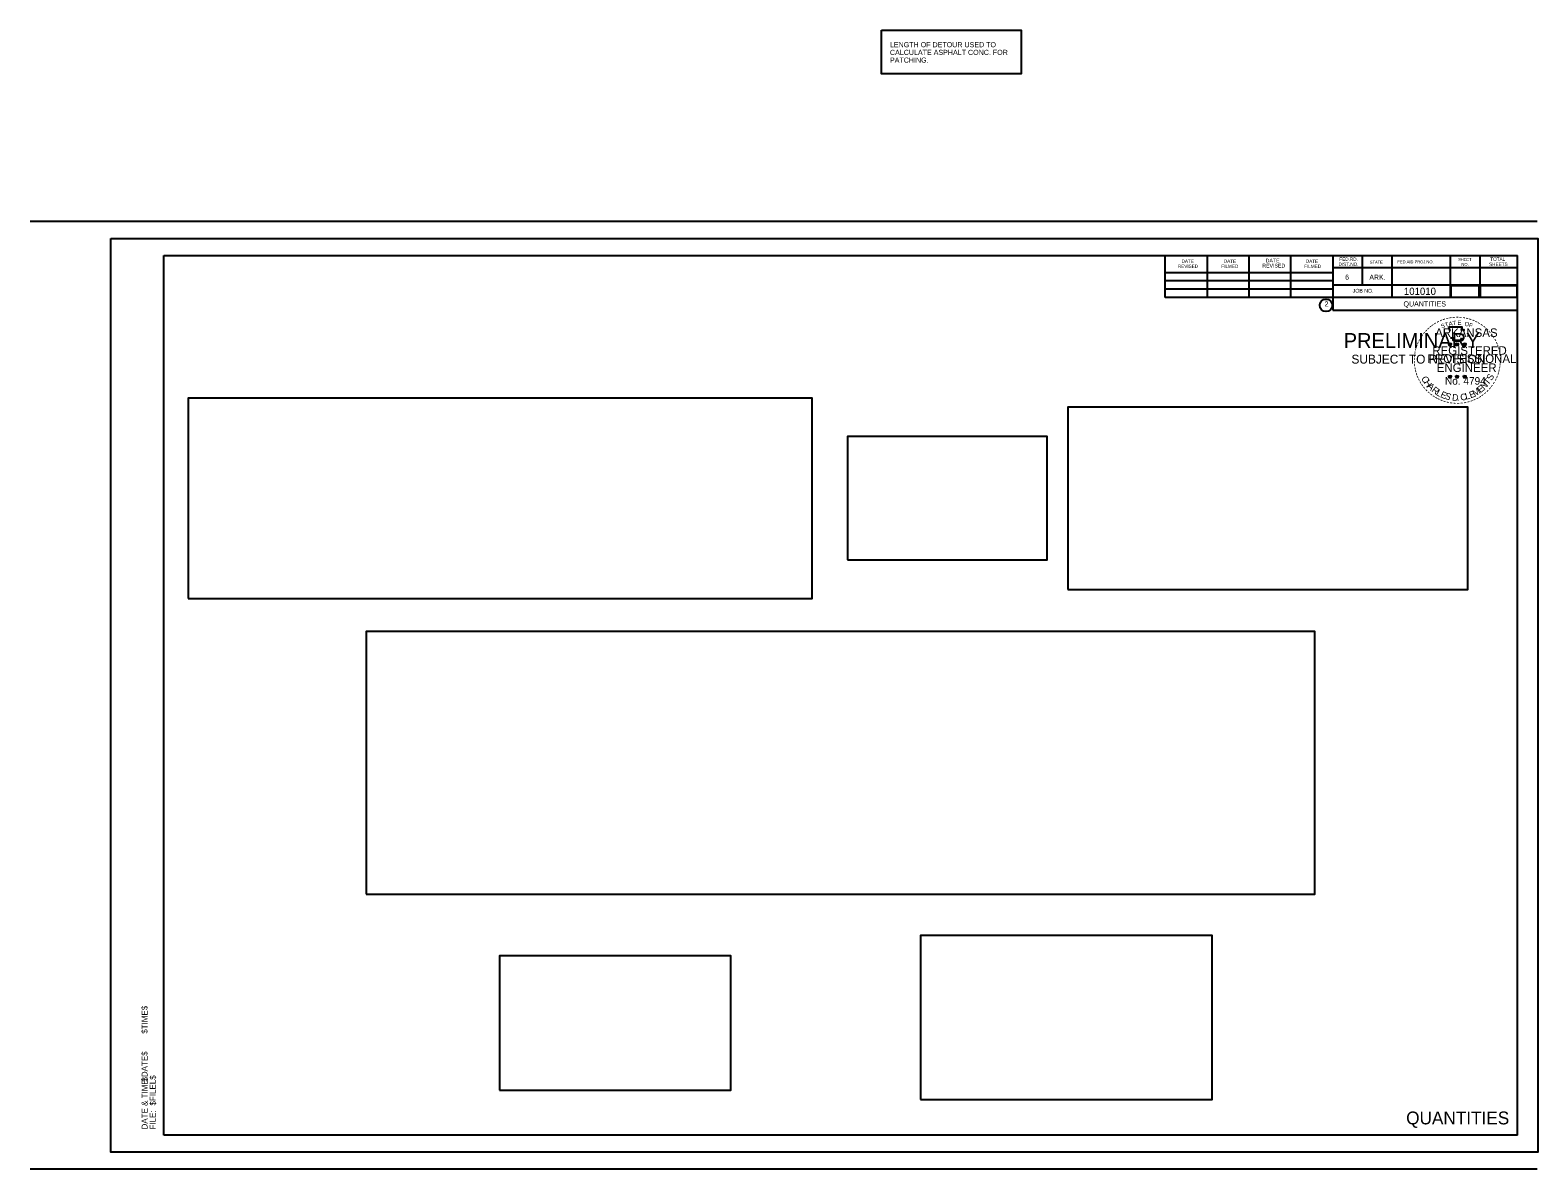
# Model space of a CAD drawing. Extents: x 9844 to 18514, y 8651 to 12569.
# Drawn here: x 13382 to 15142, y 9961 to 11290 of the extents above; entities that cross this region are included whole.
import ezdxf

# ---------------------------------------------------------------- set-up
doc = ezdxf.new("R2010")
doc.units = 0
for name, color, linetype in [('90% COMMENT', 7, 'Continuous'), ('Default', 7, 'Continuous'), ('Quantities', 7, 'Continuous'), ('R_Border Notes', 7, 'Continuous'), ('R_No Plot', 7, 'Continuous'), ('STAMP_PE_CRAFTON-SIGNATURE', 7, 'Continuous'), ('STAMP_PE_SEAL-INFO', 7, 'Continuous'), ('STAMP_PE_TXT', 7, 'Continuous'), ('STAMP_PRELIMINARY', 7, 'Continuous'), ('Total_Pages', 7, 'Continuous')]:
    doc.layers.add(name, color=color, linetype=linetype)

msp = doc.modelspace()

# ---------------------------------------------------------------- linework, layer by layer
at = {"layer": '90% COMMENT'}
msp.add_lwpolyline([(14375.9, 11290.3), (14539, 11290.3), (14539, 11239.1), (14375.9, 11239.1)], close=True, dxfattribs=at)
at = {"layer": 'Quantities'}
for points in [[(13566.2, 10626.8), (14294.8, 10626.8), (14294.8, 10860.6), (13566.2, 10860.6)], [(14593.6, 10637.2), (15060.8, 10637.2), (15060.8, 10850.2), (14593.6, 10850.2)], [(14336.3, 10671.6), (14569.6, 10671.6), (14569.6, 10815.8), (14336.3, 10815.8)], [(13774.3, 10281.4), (14882.1, 10281.4), (14882.1, 10588.1), (13774.3, 10588.1)], [(14421.4, 10041.5), (14762, 10041.5), (14762, 10233.2), (14421.4, 10233.2)], [(13929.7, 10052.3), (14199.9, 10052.3), (14199.9, 10209.4), (13929.7, 10209.4)]]:
    msp.add_lwpolyline(points, close=True, dxfattribs=at)
at = {"layer": 'R_No Plot'}
msp.add_lwpolyline([(15040.7, 10978.6), (15074, 10978.6), (15074, 10991.9), (15040.7, 10991.9)], close=True, dxfattribs=at)
at = {"layer": 'STAMP_PE_SEAL-INFO'}
msp.add_lwpolyline([(13475.8, 11046.8), (15142.5, 11046.8), (15142.5, 9980.1), (13475.8, 9980.1)], close=True, dxfattribs=at)
at = {"layer": 'STAMP_PE_TXT'}
for p, q in [((15038.1, 10924), (15039.8, 10923.5)), ((15038.1, 10924), (15039.4, 10923.8)), ((15038.1, 10924), (15039.3, 10923.4)), ((15038.8, 10922), (15039.8, 10923.5)), ((15038.8, 10922), (15039.4, 10923.2)), ((15038.8, 10922), (15039.8, 10923.1)), ((15039.8, 10925.3), (15039.6, 10924.1)), ((15039.8, 10923.5), (15039.8, 10925.3)), ((15039.8, 10925.3), (15040.1, 10924.1)), ((15041.6, 10924), (15039.8, 10923.5)), ((15040.9, 10922), (15039.8, 10923.5)), ((15040.9, 10922), (15039.8, 10923.1)), ((15041.6, 10924), (15040.2, 10923.8)), ((15040.9, 10922), (15040.2, 10923.5)), ((15041.6, 10924), (15040.6, 10923.5)), ((15046.5, 10924), (15048.2, 10923.5)), ((15046.5, 10924), (15047.7, 10923.8)), ((15046.5, 10924), (15047.6, 10923.4)), ((15047.1, 10922), (15048.2, 10923.5)), ((15047.1, 10922), (15047.7, 10923.2)), ((15047.1, 10922), (15048.2, 10923.1)), ((15048.2, 10925.3), (15048, 10924.1)), ((15048.2, 10923.5), (15048.2, 10925.3)), ((15048.2, 10925.3), (15048.4, 10924.1)), ((15049.9, 10924), (15048.2, 10923.5)), ((15049.3, 10922), (15048.2, 10923.5)), ((15049.3, 10922), (15048.2, 10923.1)), ((15049.9, 10924), (15048.5, 10923.8)), ((15049.3, 10922), (15048.6, 10923.5)), ((15049.9, 10924), (15048.9, 10923.5)), ((15055.3, 10924), (15057, 10923.4)), ((15055.3, 10924), (15056.5, 10923.8)), ((15055.3, 10924), (15056.5, 10923.4)), ((15055.9, 10921.9), (15057, 10923.4)), ((15055.9, 10921.9), (15056.6, 10923.2)), ((15055.9, 10921.9), (15057, 10923)), ((15057, 10925.3), (15056.8, 10924)), ((15057, 10923.4), (15057, 10925.3)), ((15057, 10925.3), (15057.3, 10924)), ((15058.8, 10924), (15057, 10923.4)), ((15058.1, 10921.9), (15057, 10923.4)), ((15058.1, 10921.9), (15057, 10923)), ((15058.8, 10924), (15057.3, 10923.7)), ((15058.1, 10921.9), (15057.4, 10923.4)), ((15058.8, 10924), (15057.7, 10923.5)), ((15038.1, 10886.2), (15039.8, 10885.6)), ((15038.1, 10886.2), (15039.3, 10886)), ((15038.1, 10886.2), (15039.3, 10885.6)), ((15038.7, 10884.1), (15039.8, 10885.6)), ((15038.7, 10884.1), (15039.4, 10885.4)), ((15038.7, 10884.1), (15039.8, 10885.2)), ((15039.8, 10887.4), (15039.6, 10886.2)), ((15039.8, 10885.6), (15039.8, 10887.4)), ((15039.8, 10887.4), (15040.1, 10886.2)), ((15041.6, 10886.2), (15039.8, 10885.6)), ((15040.9, 10884.1), (15039.8, 10885.6)), ((15040.9, 10884.1), (15039.8, 10885.2)), ((15041.6, 10886.2), (15040.1, 10885.9)), ((15040.9, 10884.1), (15040.2, 10885.6)), ((15041.6, 10886.2), (15040.5, 10885.7)), ((15046.4, 10886.2), (15048.2, 10885.6)), ((15046.4, 10886.2), (15047.7, 10886)), ((15046.4, 10886.2), (15047.6, 10885.6)), ((15047.1, 10884.1), (15048.2, 10885.6)), ((15047.1, 10884.1), (15047.7, 10885.4)), ((15047.1, 10884.1), (15048.2, 10885.2)), ((15048.2, 10887.4), (15048, 10886.2)), ((15048.2, 10885.6), (15048.2, 10887.4)), ((15048.2, 10887.4), (15048.4, 10886.2)), ((15049.9, 10886.2), (15048.2, 10885.6)), ((15049.2, 10884.1), (15048.2, 10885.6)), ((15049.2, 10884.1), (15048.2, 10885.2)), ((15049.9, 10886.2), (15048.5, 10885.9)), ((15049.2, 10884.1), (15048.6, 10885.6)), ((15049.9, 10886.2), (15048.9, 10885.7)), ((15055.3, 10886.1), (15057, 10885.6)), ((15055.3, 10886.1), (15056.5, 10885.9)), ((15055.3, 10886.1), (15056.4, 10885.5)), ((15055.9, 10884.1), (15057, 10885.6)), ((15055.9, 10884.1), (15056.6, 10885.3)), ((15055.9, 10884.1), (15057, 10885.2)), ((15057, 10887.4), (15056.8, 10886.1)), ((15057, 10885.6), (15057, 10887.4)), ((15057, 10887.4), (15057.3, 10886.1)), ((15058.7, 10886.1), (15057, 10885.6)), ((15058.1, 10884.1), (15057, 10885.6)), ((15058.1, 10884.1), (15057, 10885.2)), ((15058.7, 10886.1), (15057.3, 10885.9)), ((15058.1, 10884.1), (15057.4, 10885.5)), ((15058.7, 10886.1), (15057.7, 10885.6))]:
    msp.add_line(p, q, dxfattribs=at)
for points in [[(15038.3, 10943.4), (15039.7, 10939.3)], [(15055.9, 10938.8), (15056.6, 10940.2), (15053.1, 10940.1), (15053.9, 10943.4), (15038.3, 10943.4)], [(15039.8, 10925.3), (15040.9, 10922), (15038.1, 10924), (15041.6, 10924), (15038.8, 10922), (15039.8, 10925.3)], [(15040.8, 10931.3), (15040.8, 10930.9), (15043.6, 10930.8), (15043.3, 10928.4), (15052.7, 10928.4), (15053.7, 10931.1)], [(15048.2, 10925.3), (15049.3, 10922), (15046.5, 10924), (15049.9, 10924), (15047.1, 10922), (15048.2, 10925.3)], [(15057, 10925.3), (15058.1, 10921.9), (15055.3, 10924), (15058.8, 10924), (15055.9, 10921.9), (15057, 10925.3)], [(15039.8, 10887.4), (15040.9, 10884.1), (15038.1, 10886.2), (15041.6, 10886.2), (15038.7, 10884.1), (15039.8, 10887.4)], [(15048.2, 10887.4), (15049.2, 10884.1), (15046.4, 10886.2), (15049.9, 10886.2), (15047.1, 10884.1), (15048.2, 10887.4)], [(15057, 10887.4), (15058.1, 10884.1), (15055.3, 10886.1), (15058.7, 10886.1), (15055.9, 10884.1), (15057, 10887.4)]]:
    msp.add_lwpolyline(points, dxfattribs=at)
for centre, radius in [((15039.8, 10923.5), 0.861), ((15039.8, 10923.5), 0.723), ((15039.8, 10923.5), 0.579), ((15039.8, 10923.5), 0.495), ((15039.8, 10923.5), 0.374), ((15039.8, 10923.5), 0.248), ((15039.8, 10923.5), 0.148), ((15048.2, 10923.5), 0.861), ((15048.2, 10923.5), 0.723), ((15048.2, 10923.5), 0.579), ((15048.2, 10923.5), 0.495), ((15048.2, 10923.5), 0.374), ((15048.2, 10923.5), 0.248), ((15048.2, 10923.5), 0.148), ((15057, 10923.4), 0.861), ((15057, 10923.4), 0.723), ((15057, 10923.4), 0.579), ((15057, 10923.4), 0.495), ((15057, 10923.4), 0.374), ((15057, 10923.4), 0.248), ((15057, 10923.4), 0.148), ((15039.8, 10885.6), 0.861), ((15039.8, 10885.6), 0.723), ((15039.8, 10885.6), 0.579), ((15039.8, 10885.6), 0.495), ((15039.8, 10885.6), 0.374), ((15039.8, 10885.6), 0.248), ((15039.8, 10885.6), 0.148), ((15048.2, 10885.6), 0.861), ((15048.2, 10885.6), 0.723), ((15048.2, 10885.6), 0.579), ((15048.2, 10885.6), 0.495), ((15048.2, 10885.6), 0.374), ((15048.2, 10885.6), 0.248), ((15048.2, 10885.6), 0.148), ((15057, 10885.6), 0.861), ((15057, 10885.6), 0.723), ((15057, 10885.6), 0.579), ((15057, 10885.6), 0.495), ((15057, 10885.6), 0.374), ((15057, 10885.6), 0.248), ((15057, 10885.6), 0.148)]:
    msp.add_circle(centre, radius, dxfattribs=at)
at = {"layer": 'STAMP_PRELIMINARY'}
for p, q in [((15141.7, 11066.7), (13381.7, 11066.7)), ((13537.8, 11027.3), (15118.7, 11027.3)), ((13537.8, 10000), (13537.8, 11027.3)), ((14300.4, 11026), (14300.4, 11026)), ((14300.4, 11026), (14300.4, 11026)), ((14707.4, 10977.9), (14707.4, 11027.3)), ((14756.7, 10977.9), (14756.7, 11026.3)), ((14805.5, 10977.9), (14805.5, 11026.3)), ((14853.9, 10977.9), (14853.9, 11026.3)), ((14903.2, 11027.3), (14903.2, 10963.3)), ((14937.4, 11027.3), (14937.4, 10992.6)), ((14972.1, 11027.3), (14972.1, 10977.9)), ((15040, 11027.3), (15040, 10977.9)), ((15074.7, 11027.3), (15074.7, 10977.9)), ((15118.7, 10000), (15118.7, 11027.3)), ((14707.4, 11007.2), (14903.2, 11007.2)), ((15118.7, 11012.6), (14903.2, 11012.6)), ((15118.7, 11012.7), (15118.7, 11012.7)), ((14707.4, 10997.9), (14903.2, 10997.9)), ((14707.4, 10988.2), (14903.2, 10988.2)), ((15118.7, 10992.6), (14903.2, 10992.6)), ((15118.7, 10977.9), (14707.4, 10977.9)), ((14903.2, 10963.3), (15118.7, 10963.3)), ((15118.7, 10000), (13537.8, 10000)), ((13381.7, 9960.6), (15141.7, 9960.6))]:
    msp.add_line(p, q, dxfattribs=at)
msp.add_circle((14895.1, 10969), 7.33, dxfattribs=at)
at = {"layer": 'Total_Pages'}
msp.add_lwpolyline([(15075.2, 10978.6), (15118.2, 10978.6), (15118.2, 10991.9), (15075.2, 10991.9)], close=True, dxfattribs=at)

# ---------------------------------------------------------------- texts
at = {"layer": '90% COMMENT'}
for s, p in [('LENGTH OF DETOUR USED TO', (14385.8, 11270.3)), ('CALCULATE ASPHALT CONC. FOR', (14385.8, 11261.3)), ('PATCHING.', (14385.8, 11252.3))]:
    msp.add_text(s, height=6, dxfattribs=at).set_placement(p)
at = {"layer": 'Default'}
for s, height, p in [('$TIME$', 6.98, (13518.8, 10118.4)), ('$DATE$', 6.98, (13518.8, 10062.5)), ('DATE & TIME:', 6.984, (13518.8, 10006.6)), ('$FILEL$', 6.98, (13528.4, 10034.5)), ('FILE: ', 6.98, (13528.4, 10006.6))]:
    msp.add_text(s, height=height, rotation=90, dxfattribs=at).set_placement(p)
at = {"layer": 'R_Border Notes'}
for s, height, p in [('101010', 8.4, (14986, 10981.1)), ('QUANTITIES', 6, (14985.5, 10967.6))]:
    msp.add_text(s, height=height, dxfattribs=at).set_placement(p)
at = {"layer": 'STAMP_PE_CRAFTON-SIGNATURE'}
for s, height, p in [('PRELIMINARY', 17.5, (14915.7, 10919)), ('SUBJECT TO REVISION', 10.376, (14924.8, 10900.9))]:
    msp.add_text(s, height=height, dxfattribs=at).set_placement(p)
at = {"layer": 'STAMP_PE_TXT'}
for s, height, rotation, p in [('-', 8, 24.3072, (15028.9, 10947.7)), ('-', 8, 19.1761, (15032, 10949.1)), ('-', 8, 13.6302, (15035.8, 10950.3)), ('-', 8, 10.2193, (15039.2, 10951.1)), ('-', 8, 5.8968, (15042.8, 10951.6)), ('-', 8, 0.1862, (15046.7, 10952)), ('-', 8, 357.743, (15050.3, 10951.9)), ('-', 8, 352.1617, (15054, 10951.6)), ('-', 8, 347.2049, (15057.6, 10951.1)), ('-', 8, 342.3362, (15060.8, 10950.3)), ('-', 8, 337.8551, (15064.5, 10949.2)), ('-', 8, 54.2325, (15009, 10930.7)), ('-', 8, 50.6142, (15011, 10933.5)), ('-', 8, 48.4231, (15013.1, 10935.9)), ('-', 8, 42.9622, (15015.3, 10938.3)), ('-', 8, 38.9507, (15017.5, 10940.4)), ('-', 8, 36.2317, (15019.8, 10942.3)), ('-', 8, 34.0636, (15022.7, 10944.3)), ('-', 8, 28.7918, (15025.7, 10946.1)), ('S', 5, 21.594, (15030.1, 10941.8)), ('T', 5, 16.4036, (15034.7, 10943.5)), ('A', 5, 11.2132, (15038.8, 10944.7)), ('T', 5, 6.0228, (15043, 10945.6)), ('E', 5, 0.8323, (15048.6, 10946.1)), ('O', 5, 350.4515, (15056.6, 10945.1)), ('F', 5, 340.0707, (15061.3, 10943.9)), ('-', 8, 334.1211, (15067.6, 10947.8)), ('-', 8, 329.6409, (15070.5, 10946.4)), ('-', 8, 325.8627, (15073.7, 10944.6)), ('-', 8, 320.5297, (15076.8, 10942.5)), ('-', 8, 315.5786, (15079.8, 10940)), ('-', 8, 309.8797, (15082.6, 10937.3)), ('-', 8, 306.6522, (15085.3, 10934.3)), ('-', 8, 75.461, (15002.4, 10915.2)), ('-', 8, 72.3945, (15003.4, 10918.8)), ('-', 8, 67.7743, (15004.5, 10921.9)), ('-', 8, 62.8713, (15005.8, 10925)), ('-', 8, 58.0706, (15007.3, 10928)), ('-', 7, 303.6753, (15087.7, 10931.4)), ('-', 8, 299.6684, (15089.3, 10928.4)), ('-', 8, 294.6628, (15090.9, 10925.3)), ('-', 8, 290.5728, (15092.2, 10922.5)), ('-', 8, 285.1233, (15093.4, 10919.6)), ('-', 8, 89.0622, (15001.2, 10904.7)), ('-', 8, 94.1959, (15001.4, 10901.1)), ('-', 8, 98.9479, (15001.8, 10897.7)), ('-', 8, 85.1863, (15001.4, 10908.2)), ('-', 8, 81.2013, (15001.7, 10911.6)), ('-', 8, 280.5493, (15094.4, 10915.9)), ('-', 8, 276.5962, (15095.2, 10912)), ('-', 8, 263.5172, (15095.5, 10901.9)), ('-', 8, 274.3301, (15095.5, 10908.4)), ('-', 8, 269.9407, (15095.6, 10905.2)), ('-', 8, 101.7149, (15002.5, 10894.1)), ('-', 8, 105.4578, (15003.3, 10891.1)), ('-', 8, 109.0874, (15004.3, 10887.9)), ('-', 8, 114.0643, (15005.6, 10884.9)), ('-', 8, 115.7289, (15007.1, 10881.9)), ('C', 7.7, 296.9133, (15006, 10883.9)), ('H', 7.7, 303.2799, (15008.9, 10878.7)), ('T', 7.7, 51.5114, (15084.6, 10875.1)), ('S', 7.7, 57.878, (15088.3, 10880.3)), ('-', 8, 244.6197, (15091.3, 10885.1)), ('-', 8, 247.8887, (15092.6, 10888.3)), ('-', 8, 255.7626, (15093.7, 10891.8)), ('-', 8, 255.7626, (15094.6, 10895.3)), ('-', 8, 260.9953, (15095.2, 10898.6)), ('-', 8, 120.4471, (15008.9, 10878.9)), ('-', 8, 125.8934, (15010.9, 10876.1)), ('-', 8, 130.7181, (15013.2, 10873.4)), ('-', 8, 134.2238, (15015.8, 10870.6)), ('A', 7.7, 316.013, (15012.6, 10873.6)), ('-', 8, 138.9338, (15018.5, 10868.3)), ('-', 8, 144.6463, (15021.2, 10866.3)), ('R', 7.7, 322.3796, (15017.7, 10868.7)), ('L', 7.7, 328.7461, (15022.8, 10864.9)), ('E', 7.7, 335.1127, (15027.9, 10862.1)), ('S', 7.7, 341.4792, (15033.2, 10860)), ('D', 7.7, 354.2124, (15042, 10857.9)), ('C', 7.7, 6.9455, (15052.4, 10857.7)), ('L', 7.7, 13.3121, (15058.4, 10858.7)), ('E', 7.7, 19.6786, (15063.9, 10860.3)), ('M', 7.7, 32.4117, (15069, 10862.1)), ('E', 7.7, 38.7783, (15075.4, 10866.2)), ('N', 7.7, 45.1449, (15079.8, 10869.9)), ('-', 8, 215.7363, (15077.4, 10867.6)), ('-', 8, 221.0851, (15080.2, 10869.9)), ('-', 8, 225.7653, (15082.8, 10872.5)), ('-', 8, 231.2538, (15085.2, 10875.3)), ('-', 8, 233.8452, (15087.3, 10878.1)), ('-', 8, 239.0712, (15089.3, 10881.4)), ('-', 8, 148.0898, (15024, 10864.4)), ('-', 8, 151.5704, (15026.9, 10862.8)), ('-', 8, 154.6002, (15029.5, 10861.6)), ('-', 8, 158.5612, (15032.7, 10860.3)), ('-', 8, 162.7983, (15036.1, 10859.2)), ('-', 8, 167.5555, (15039.7, 10858.4)), ('-', 8, 173.1155, (15043.5, 10857.9)), ('-', 8, 176.5183, (15047.3, 10857.6)), ('-', 8, 181.5918, (15051, 10857.7)), ('.', 7.7, 0.5789, (15047.9, 10857.5)), ('-', 8, 185.8167, (15055, 10858.1)), ('-', 8, 191.2858, (15058.7, 10858.7)), ('-', 8, 195.4743, (15062.4, 10859.7)), ('-', 8, 200.7184, (15065.7, 10860.9)), ('-', 8, 204.2516, (15068.8, 10862.3)), ('-', 8, 207.3568, (15072, 10863.9)), ('-', 8, 212.2491, (15074.8, 10865.6))]:
    msp.add_text(s, height=height, rotation=rotation, dxfattribs=at).set_placement(p)
for s, height, p in [('ARKANSAS', 10, (15022.6, 10932)), ('REGISTERED', 10, (15019.2, 10911.2)), ('PROFESSIONAL', 10, (15013.4, 10901.7)), ('ENGINEER', 10, (15024.4, 10891.1)), ('No. 4794', 8.78, (15034, 10876.3))]:
    msp.add_text(s, height=height, dxfattribs=at).set_placement(p)
at = {"layer": 'STAMP_PRELIMINARY'}
for s, height, p in [('DATE', 3.91, (14726.4, 11018.5)), ('DATE', 3.91, (14775.7, 11018.5)), ('DATE', 4.4, (14824.6, 11019)), ('DATE', 3.91, (14871.5, 11018.5)), ('FED.RD.', 3.91, (14910.6, 11020.9)), ('SHEET', 3.42, (15049.3, 11020.9)), ('TOTAL', 3.91, (15086.9, 11020.9)), ('REVISED', 3.91, (14722, 11012.6)), ('FILMED', 3.91, (14772.8, 11012.6)), ('REVISED', 4.4, (14820.7, 11013.1)), ('FILMED', 3.91, (14869.5, 11012.6)), ('DIST.NO.', 3.91, (14909.6, 11015)), ('6', 5.86, (14917.4, 10998.9)), ('STATE', 3.42, (14946.2, 11017.5)), ('FED.AID PROJ.NO.', 3.42, (14978.5, 11018)), ('NO.', 3.42, (15053.2, 11015)), ('SHEETS', 3.91, (15085.5, 11015)), ('JOB NO.', 4.4, (14926.2, 10983.8)), ('ARK.', 5.86, (14945.7, 10998.9)), ('2', 5.86, (14893.5, 10967.7)), ('QUANTITIES', 15, (14988.7, 10012.5))]:
    msp.add_text(s, height=height, dxfattribs=at).set_placement(p)

doc.saveas('drawing.dxf')
